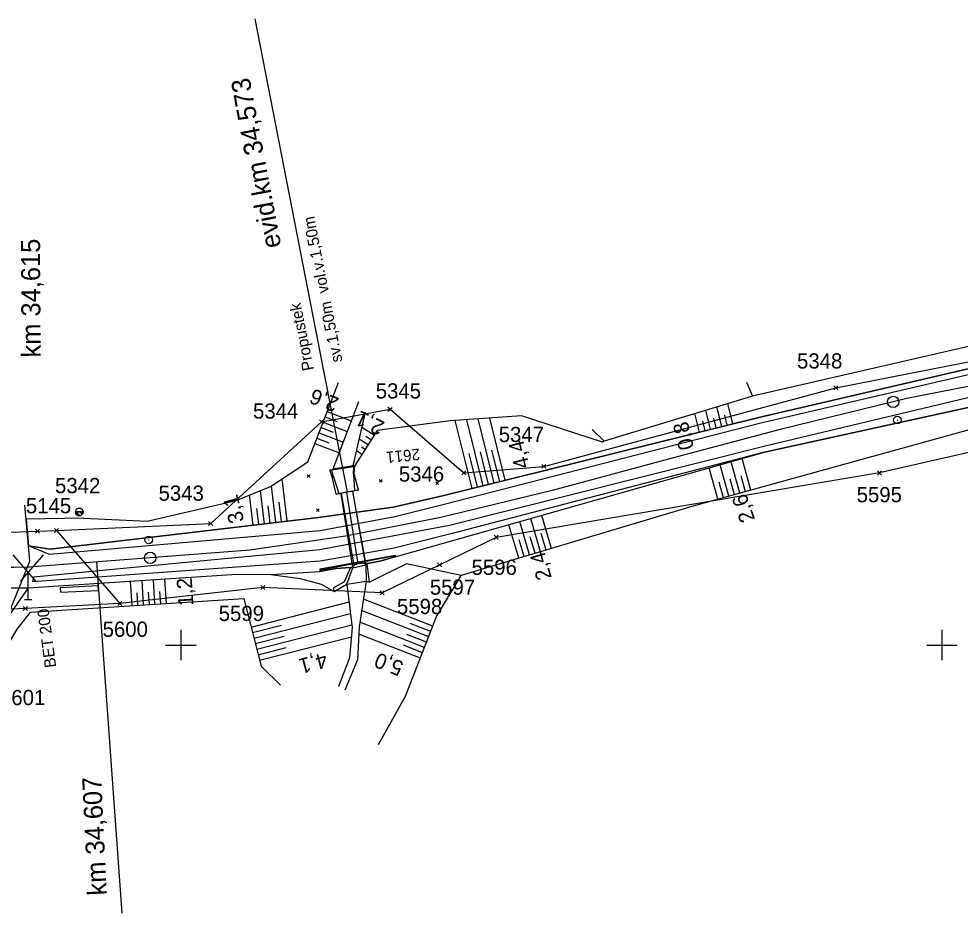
# Model space of a CAD drawing. Extents: x -805730 to -804640, y -1150889 to -1150366.
# Drawn here: x -805421.3 to -805297.6, y -1150735.2 to -1150617.7 of the extents above; entities that cross this region are included whole.
import ezdxf

# ---------------------------------------------------------------- set-up
doc = ezdxf.new("R2010")
doc.units = 0
for name, color, linetype in [('0381KM032-037P - Vrstva 1', 7, 'Continuous'), ('0381KM032-037P - Vrstva 17', 7, 'Continuous'), ('0381KM032-037P - Vrstva 19', 7, 'Continuous'), ('0381KM032-037P - Vrstva 36', 7, 'Continuous'), ('0381KM032-037P - Vrstva 4', 7, 'Continuous'), ('0381KM032-037P - Vrstva 48', 7, 'Continuous'), ('0381KM032-037P - Vrstva 49', 7, 'Continuous'), ('0381KM032-037P - Vrstva 51', 7, 'Continuous'), ('0381KM032-037P - Vrstva 55', 7, 'Continuous'), ('0381KM032-037P - Vrstva 57', 7, 'Continuous'), ('0381KM032-037P - Vrstva 7', 7, 'Continuous'), ('0381KM032-037P - Vrstva 9', 7, 'Continuous'), ('krizky_1000 - Vrstva 1', 7, 'Continuous'), ('szdc - hran DP', 7, 'Continuous'), ('szdc - szdc_cislo', 7, 'Continuous'), ('szdc - szdc_krizek', 7, 'Continuous')]:
    doc.layers.add(name, color=color, linetype=linetype)

msp = doc.modelspace()

# ---------------------------------------------------------------- linework, layer by layer
at = {"layer": '0381KM032-037P - Vrstva 1'}
for points in [[(-805262.34, -1150660.99), (-805275.34, -1150662.5), (-805288.75, -1150664.54), (-805289.64, -1150664.68), (-805304.6, -1150667.62), (-805306.42, -1150668.06)], [(-805306.42, -1150668.06), (-805321.24, -1150671.67), (-805334.8, -1150675.29), (-805351.21, -1150679.7), (-805364.56, -1150682.93)], [(-805364.56, -1150682.93), (-805366.04, -1150683.29), (-805378.36, -1150685.71), (-805390.91, -1150687.55), (-805419.96, -1150689.78), (-805423.96, -1150689.8), (-805433.29, -1150689.8), (-805447.38, -1150689.21), (-805460.61, -1150688.07), (-805473.24, -1150686.41), (-805486.12, -1150684.11), (-805496.07, -1150681.84)]]:
    msp.add_lwpolyline(points, dxfattribs=at)
at = {"layer": '0381KM032-037P - Vrstva 17'}
msp.add_lwpolyline([(-805325.7, -1150665.45), (-805324.89, -1150667.28), (-805344.39, -1150673.21), (-805345.97, -1150671.67)], dxfattribs=at)
at = {"layer": '0381KM032-037P - Vrstva 19'}
for p, q in [((-805378.12, -1150679.9), (-805390.23, -1150617.73)), ((-805380.17, -1150676.97), (-805377.25, -1150676.53)), ((-805377.12, -1150676.41), (-805377.25, -1150676.53)), ((-805377.23, -1150677.51), (-805377.12, -1150676.41)), ((-805380.42, -1150677), (-805380.17, -1150676.97)), ((-805380.12, -1150677.92), (-805380.42, -1150677)), ((-805378.95, -1150680.08), (-805377.25, -1150689.53)), ((-805377.4, -1150689.87), (-805378.93, -1150680.13)), ((-805378.22, -1150679.93), (-805376.73, -1150689.34)), ((-805377.44, -1150679.8), (-805375.79, -1150689.3)), ((-805377.44, -1150679.84), (-805375.71, -1150689.44)), ((-805371.83, -1150688.19), (-805372.13, -1150688.5)), ((-805381.67, -1150690), (-805381.78, -1150690.33)), ((-805425.41, -1150692.47), (-805420.07, -1150692.47)), ((-805378.2, -1150692.01), (-805375.64, -1150691.6))]:
    msp.add_line(p, q, dxfattribs=at)
for points in [[(-805379.92, -1150677.91), (-805380.17, -1150676.97), (-805380.03, -1150676.88), (-805377.35, -1150676.44)], [(-805377.3, -1150677.55), (-805377.25, -1150676.53), (-805377.35, -1150676.44)], [(-805377.44, -1150679.8), (-805377.44, -1150679.84), (-805377.2, -1150679.71), (-805376.64, -1150679.64), (-805377.23, -1150677.51), (-805377.3, -1150677.55), (-805377.2, -1150679.71)], [(-805379.6, -1150680.17), (-805380.12, -1150677.92), (-805379.92, -1150677.91), (-805379.23, -1150680.09)], [(-805376.64, -1150679.64), (-805379.6, -1150680.17), (-805379.23, -1150680.09), (-805378.93, -1150680.13), (-805378.95, -1150680.08)], [(-805377.25, -1150689.53), (-805377.4, -1150689.87), (-805377.71, -1150689.8), (-805379.64, -1150689.94), (-805381.78, -1150690.33), (-805381.61, -1150690.16), (-805381.67, -1150690), (-805371.83, -1150688.19), (-805371.8, -1150688.29), (-805381.61, -1150690.16)], [(-805371.8, -1150688.29), (-805372.13, -1150688.5), (-805373.84, -1150688.99), (-805375.5, -1150689.3), (-805375.71, -1150689.44), (-805375.79, -1150689.3)], [(-805377.71, -1150689.8), (-805378.52, -1150691.68), (-805379.98, -1150692.52), (-805379.86, -1150692.97), (-805378.2, -1150692.01), (-805377.4, -1150689.87)], [(-805375.71, -1150689.44), (-805375.64, -1150691.6), (-805375.2, -1150691.74), (-805375.5, -1150689.3)]]:
    msp.add_lwpolyline(points, dxfattribs=at)
for centre, major_axis, ratio, start_param, end_param in [((-805378.2, -1150679.95), (-0.792, -0.149), 0.032025, 3.416243, 5.97224), ((-805376.52, -1150689.46), (-0.761, -0.129), 0.198559, 3.38498, 5.924926)]:
    msp.add_ellipse(centre, major_axis=major_axis, ratio=ratio, start_param=start_param, end_param=end_param, dxfattribs=at)
at = {"layer": '0381KM032-037P - Vrstva 36'}
for p, q in [((-805413.84, -1150682.5), (-805412.84, -1150682.5)), ((-805412.84, -1150682.5), (-805413.84, -1150682.5)), ((-805413.28, -1150683), (-805413.77, -1150682.5)), ((-805412.94, -1150682.8), (-805413.24, -1150682.5))]:
    msp.add_line(p, q, dxfattribs=at)
msp.add_circle((-805413.34, -1150682.5), 0.503, dxfattribs=at)
msp.add_arc((-805413.34, -1150682.5), 0.503, 180, 0, dxfattribs=at)
at = {"layer": '0381KM032-037P - Vrstva 4'}
for p, q in [((-805422.05, -1150688.15), (-805419.05, -1150691.65)), ((-805421.05, -1150691.65), (-805418.05, -1150688.15)), ((-805423.96, -1150689.8), (-805419.82, -1150689.74)), ((-805420.05, -1150694), (-805420.05, -1150690.5)), ((-805420.55, -1150694), (-805419.55, -1150694))]:
    msp.add_line(p, q, dxfattribs=at)
for points in [[(-805228.99, -1150656.61), (-805257.13, -1150657.62), (-805260.23, -1150658.03), (-805264.49, -1150659.11), (-805283.86, -1150661.58), (-805295.64, -1150663.5), (-805324.06, -1150670.09), (-805365.63, -1150680.4), (-805372.09, -1150681.89), (-805381.91, -1150683.24), (-805417.14, -1150687.42), (-805420, -1150686.97)], [(-805212.28, -1150657.22), (-805228.89, -1150657.63), (-805258.88, -1150659.27), (-805264.46, -1150659.8), (-805283.61, -1150662.28), (-805295.6, -1150664.3), (-805323.97, -1150670.91), (-805365.39, -1150681.52), (-805371.9, -1150683.14), (-805381.67, -1150685.01), (-805417.27, -1150688.09), (-805420, -1150686.97)], [(-805212.01, -1150660.08), (-805229.13, -1150661), (-805258.58, -1150662.1), (-805264.18, -1150662.62), (-805283.43, -1150665.36), (-805294.93, -1150667.11), (-805323.21, -1150673.86), (-805364.72, -1150684.28), (-805371.95, -1150685.67), (-805381.73, -1150687.49), (-805401.63, -1150689.36), (-805419.33, -1150691.07), (-805419.49, -1150691.68)], [(-805225.57, -1150661.42), (-805229.16, -1150661.68), (-805258.55, -1150662.93), (-805264.16, -1150663.27), (-805283.37, -1150665.88), (-805323.33, -1150674.68), (-805364.37, -1150685.33), (-805371.95, -1150687.26), (-805381.71, -1150688.97), (-805419.49, -1150691.68)]]:
    msp.add_lwpolyline(points, dxfattribs=at)
at = {"layer": '0381KM032-037P - Vrstva 48'}
for p, q in [((-805330.39, -1150671.66), (-805331.01, -1150669.14)), ((-805328.93, -1150671.3), (-805329.57, -1150668.7)), ((-805327.47, -1150670.94), (-805328.14, -1150668.27)), ((-805381.03, -1150670.01), (-805379.45, -1150670.62)), ((-805380.75, -1150669.31), (-805377.62, -1150670.53)), ((-805360.28, -1150679.07), (-805362.44, -1150670.39)), ((-805358.83, -1150678.71), (-805360.92, -1150670.29)), ((-805357.37, -1150678.35), (-805359.4, -1150670.18)), ((-805331.84, -1150672.02), (-805332.45, -1150669.58)), ((-805329.66, -1150671.48), (-805329.97, -1150670.2)), ((-805328.2, -1150671.12), (-805328.53, -1150669.8)), ((-805381.57, -1150671.41), (-805379.99, -1150672.02)), ((-805381.3, -1150670.71), (-805378.15, -1150671.93)), ((-805374.6, -1150672.41), (-805376.2, -1150671.41)), ((-805361.74, -1150679.43), (-805363.95, -1150670.5)), ((-805331.11, -1150671.84), (-805331.42, -1150670.6)), ((-805382.11, -1150672.81), (-805380.53, -1150673.42)), ((-805381.84, -1150672.11), (-805378.68, -1150673.33)), ((-805375, -1150673.05), (-805375.68, -1150672.61)), ((-805382.38, -1150673.51), (-805379.21, -1150674.74)), ((-805375.4, -1150673.68), (-805376.55, -1150672.96)), ((-805375.8, -1150674.31), (-805376.26, -1150674.02)), ((-805376.2, -1150674.95), (-805376.9, -1150674.5)), ((-805361.01, -1150679.25), (-805362.1, -1150674.85)), ((-805359.56, -1150678.89), (-805360.62, -1150674.62)), ((-805358.1, -1150678.53), (-805359.13, -1150674.38)), ((-805327.99, -1150680.45), (-805329.14, -1150676.32)), ((-805326.55, -1150680.05), (-805327.69, -1150675.91)), ((-805325.1, -1150679.65), (-805326.25, -1150675.51)), ((-805329.44, -1150680.85), (-805330.58, -1150676.73)), ((-805325.82, -1150679.85), (-805326.4, -1150677.78)), ((-805387.51, -1150683.91), (-805388.09, -1150679.07)), ((-805386.02, -1150683.73), (-805386.68, -1150678.15)), ((-805328.71, -1150680.65), (-805329.29, -1150678.59)), ((-805327.27, -1150680.25), (-805327.84, -1150678.19)), ((-805390.49, -1150684.26), (-805390.96, -1150680.28)), ((-805389, -1150684.08), (-805389.52, -1150679.69)), ((-805386.77, -1150683.82), (-805387.08, -1150681.21)), ((-805389.75, -1150684.17), (-805389.99, -1150682.08)), ((-805388.26, -1150684), (-805388.53, -1150681.7)), ((-805354.17, -1150688.16), (-805355.47, -1150683.78)), ((-805352.73, -1150687.73), (-805354.03, -1150683.37)), ((-805351.29, -1150687.3), (-805352.58, -1150682.96)), ((-805355.6, -1150688.59), (-805356.92, -1150684.19)), ((-805354.89, -1150688.37), (-805355.54, -1150686.18)), ((-805353.45, -1150687.94), (-805354.1, -1150685.76)), ((-805352.01, -1150687.52), (-805352.66, -1150685.34)), ((-805403.39, -1150694.62), (-805403.59, -1150691.39)), ((-805401.89, -1150694.52), (-805402.09, -1150691.3)), ((-805406.38, -1150694.81), (-805406.59, -1150691.59)), ((-805404.88, -1150694.71), (-805405.09, -1150691.49)), ((-805405.63, -1150694.76), (-805405.73, -1150693.15)), ((-805404.13, -1150694.66), (-805404.24, -1150693.05)), ((-805402.64, -1150694.57), (-805402.74, -1150692.96)), ((-805390.77, -1150697.63), (-805377.9, -1150694.34)), ((-805366.89, -1150697.51), (-805376.01, -1150693.96)), ((-805390.4, -1150699.08), (-805377.71, -1150695.84)), ((-805367.43, -1150698.91), (-805376.24, -1150695.48)), ((-805390.59, -1150698.36), (-805386.75, -1150697.38)), ((-805390.03, -1150700.54), (-805377.53, -1150697.34)), ((-805367.98, -1150700.31), (-805376.48, -1150697)), ((-805367.16, -1150698.21), (-805369.85, -1150697.16)), ((-805390.21, -1150699.81), (-805386.44, -1150698.85)), ((-805368.52, -1150701.71), (-805376.62, -1150698.55)), ((-805367.71, -1150699.61), (-805370.3, -1150698.6)), ((-805389.66, -1150701.99), (-805377.59, -1150698.91)), ((-805368.25, -1150701.01), (-805370.75, -1150700.03)), ((-805389.84, -1150701.27), (-805386.15, -1150700.32))]:
    msp.add_line(p, q, dxfattribs=at)
at = {"layer": '0381KM032-037P - Vrstva 49'}
for p, q in [((-805383.32, -1150675.93), (-805379.28, -1150665.5)), ((-805376.67, -1150668.04), (-805380.03, -1150676.88)), ((-805377.35, -1150676.44), (-805375.74, -1150669.42)), ((-805374.21, -1150671.8), (-805377.12, -1150676.41)), ((-805377.35, -1150676.44), (-805380.03, -1150676.88)), ((-805377.12, -1150676.41), (-805377.35, -1150676.44)), ((-805383.03, -1150677.64), (-805383.38, -1150678)), ((-805383.38, -1150677.64), (-805383.02, -1150678)), ((-805373.92, -1150678.26), (-805373.56, -1150678.61)), ((-805373.56, -1150678.26), (-805373.91, -1150678.61)), ((-805366.14, -1150678.54), (-805366.49, -1150678.89)), ((-805366.49, -1150678.54), (-805366.13, -1150678.89)), ((-805381.8, -1150682.09), (-805382.15, -1150682.45)), ((-805382.15, -1150682.09), (-805381.8, -1150682.44))]:
    msp.add_line(p, q, dxfattribs=at)
for points in [[(-805420, -1150686.97), (-805417.14, -1150687.42), (-805381.91, -1150683.24), (-805372.09, -1150681.89), (-805365.63, -1150680.4), (-805324.06, -1150670.09), (-805295.64, -1150663.5), (-805283.86, -1150661.58), (-805264.49, -1150659.11)], [(-805372.13, -1150688.5), (-805323.33, -1150674.68), (-805283.37, -1150665.88), (-805264.16, -1150663.27), (-805258.55, -1150662.93), (-805229.16, -1150661.68), (-805225.47, -1150661.83)], [(-805296.52, -1150660.78), (-805324.89, -1150667.28), (-805344.39, -1150673.21)], [(-805229.52, -1150663.36), (-805258.94, -1150664.75), (-805264.69, -1150666.1), (-805283.13, -1150668.03), (-805332.88, -1150681.81), (-805363.18, -1150690.85)], [(-805344.39, -1150673.21), (-805344.61, -1150673.34), (-805355.22, -1150669.89), (-805364.63, -1150670.55), (-805374.21, -1150671.8)], [(-805412.74, -1150683.31), (-805404.41, -1150683.71), (-805392.74, -1150681.01), (-805388.23, -1150679.16), (-805383.32, -1150675.93)], [(-805412.74, -1150683.31), (-805420.31, -1150683.48), (-805420, -1150686.97)], [(-805420.07, -1150692.47), (-805392.63, -1150690.68), (-805388.18, -1150690.75), (-805381.78, -1150690.33), (-805379.64, -1150689.94), (-805377.71, -1150689.8), (-805377.4, -1150689.87), (-805375.71, -1150689.44), (-805375.5, -1150689.3), (-805373.84, -1150688.99), (-805372.13, -1150688.5)], [(-805363.18, -1150690.85), (-805370.35, -1150689.33), (-805375.2, -1150691.74), (-805375.64, -1150691.6)], [(-805388.18, -1150690.75), (-805384.32, -1150691.25), (-805381.55, -1150691.98), (-805379.86, -1150692.97), (-805378.2, -1150692.01), (-805377.48, -1150697.71), (-805377.85, -1150701.68), (-805379.27, -1150705.45)], [(-805374.03, -1150713.04), (-805370.47, -1150706.7), (-805366.4, -1150696.26), (-805363.18, -1150690.85)], [(-805420.07, -1150692.47), (-805422.84, -1150696.5), (-805425.52, -1150700.88)], [(-805378.2, -1150692.01), (-805375.64, -1150691.6), (-805376.57, -1150697.62), (-805376.78, -1150701.96), (-805378.44, -1150705.91)], [(-805419.74, -1150695.67), (-805391.73, -1150693.87), (-805389.46, -1150702.77), (-805386.92, -1150705.25)], [(-805423.96, -1150702.03), (-805421.5, -1150697.89), (-805419.74, -1150695.67)]]:
    msp.add_lwpolyline(points, dxfattribs=at)
at = {"layer": '0381KM032-037P - Vrstva 51'}
msp.add_lwpolyline([(-805425.52, -1150700.88), (-805422.84, -1150696.5), (-805419.83, -1150688.97), (-805420, -1150686.97), (-805420.48, -1150681.6)], dxfattribs=at)
at = {"layer": '0381KM032-037P - Vrstva 55'}
msp.add_line((-805416.34, -1150684.94), (-805408.01, -1150694.56), dxfattribs=at)
at = {"layer": '0381KM032-037P - Vrstva 7'}
for p, q in [((-805305.9, -1150670.45), (-805305.8, -1150670.45)), ((-805404.26, -1150686.19), (-805404.16, -1150686.19))]:
    msp.add_line(p, q, dxfattribs=at)
for centre, radius in [((-805306.42, -1150668.06), 0.75), ((-805305.85, -1150670.45), 0.5), ((-805404.21, -1150686.19), 0.5), ((-805404.03, -1150688.55), 0.75)]:
    msp.add_circle(centre, radius, dxfattribs=at)
at = {"layer": '0381KM032-037P - Vrstva 9'}
for p, q in [((-805411.08, -1150689.08), (-805407.73, -1150735.22)), ((-805410.84, -1150692.23), (-805415.83, -1150692.47)), ((-805415.83, -1150692.47), (-805415.8, -1150693.06)), ((-805410.84, -1150692.23), (-805410.86, -1150691.64)), ((-805410.81, -1150692.82), (-805410.84, -1150692.23)), ((-805415.8, -1150693.06), (-805410.81, -1150692.82))]:
    msp.add_line(p, q, dxfattribs=at)
at = {"layer": 'krizky_1000 - Vrstva 1'}
for points in [[(-805400, -1150698), (-805400, -1150702)], [(-805300, -1150698), (-805300, -1150702)], [(-805402, -1150700), (-805398, -1150700)], [(-805302, -1150700), (-805298, -1150700)]]:
    msp.add_lwpolyline(points, dxfattribs=at)
at = {"layer": 'szdc - hran DP'}
for p, q in [((-805313.93, -1150666.21), (-805288.99, -1150661.29)), ((-805352.32, -1150676.52), (-805313.93, -1150666.21)), ((-805267.02, -1150667.87), (-805308.19, -1150677.39)), ((-805381.52, -1150670.67), (-805372.51, -1150669.03)), ((-805372.51, -1150669.03), (-805362.8, -1150677.38)), ((-805396.07, -1150684.02), (-805381.52, -1150670.67)), ((-805362.8, -1150677.38), (-805352.32, -1150676.52)), ((-805308.19, -1150677.39), (-805358.57, -1150685.85)), ((-805416.34, -1150684.94), (-805396.07, -1150684.02)), ((-805423.42, -1150685.2), (-805418.81, -1150685.03)), ((-805418.81, -1150685.03), (-805416.34, -1150684.94)), ((-805358.57, -1150685.85), (-805365.99, -1150689.46)), ((-805365.99, -1150689.46), (-805373.55, -1150693.14)), ((-805389.21, -1150692.42), (-805408.01, -1150694.56)), ((-805373.55, -1150693.14), (-805389.21, -1150692.42)), ((-805408.01, -1150694.56), (-805420.42, -1150695.2)), ((-805420.42, -1150695.2), (-805426.08, -1150695.49))]:
    msp.add_line(p, q, dxfattribs=at)
at = {"layer": 'szdc - szdc_krizek'}
for p, q in [((-805313.67, -1150666.48), (-805314.2, -1150665.95)), ((-805314.2, -1150666.48), (-805313.67, -1150665.95)), ((-805372.24, -1150669.29), (-805372.78, -1150668.77)), ((-805372.78, -1150669.29), (-805372.24, -1150668.77)), ((-805381.26, -1150670.94), (-805381.79, -1150670.41)), ((-805381.79, -1150670.94), (-805381.26, -1150670.41)), ((-805352.06, -1150676.78), (-805352.59, -1150676.26)), ((-805352.59, -1150676.78), (-805352.06, -1150676.26)), ((-805362.54, -1150677.65), (-805363.07, -1150677.11)), ((-805363.07, -1150677.65), (-805362.54, -1150677.11)), ((-805307.93, -1150677.66), (-805308.46, -1150677.12)), ((-805308.46, -1150677.66), (-805307.93, -1150677.12)), ((-805395.81, -1150684.28), (-805396.34, -1150683.76)), ((-805396.34, -1150684.28), (-805395.81, -1150683.76)), ((-805418.55, -1150685.29), (-805419.08, -1150684.77)), ((-805419.08, -1150685.29), (-805418.55, -1150684.77)), ((-805416.08, -1150685.21), (-805416.61, -1150684.68)), ((-805416.61, -1150685.21), (-805416.08, -1150684.68)), ((-805358.31, -1150686.11), (-805358.84, -1150685.58)), ((-805358.84, -1150686.11), (-805358.31, -1150685.58)), ((-805365.72, -1150689.73), (-805366.26, -1150689.2)), ((-805366.26, -1150689.73), (-805365.72, -1150689.2)), ((-805388.95, -1150692.69), (-805389.48, -1150692.16)), ((-805389.48, -1150692.69), (-805388.95, -1150692.16)), ((-805373.29, -1150693.41), (-805373.82, -1150692.88)), ((-805373.82, -1150693.41), (-805373.29, -1150692.88)), ((-805420.16, -1150695.47), (-805420.69, -1150694.94)), ((-805420.69, -1150695.47), (-805420.16, -1150694.94)), ((-805407.74, -1150694.82), (-805408.28, -1150694.29)), ((-805408.28, -1150694.82), (-805407.74, -1150694.29))]:
    msp.add_line(p, q, dxfattribs=at)

# ---------------------------------------------------------------- texts
at = {"layer": '0381KM032-037P - Vrstva 19'}
for s, height, rotation, p in [('evid.km 34,573', 2.5, 100.6945, (-805386.78, -1150647.62)), ('sv.1,50m  vol.v.1,50m', 1.4999, 101.0532, (-805378.75, -1150662.72)), ('Propustek', 1.5, 101.1547, (-805382.51, -1150663.81)), ('BET 200', 1.5, 97.5063, (-805416.36, -1150702.88))]:
    msp.add_text(s, height=height, rotation=rotation, dxfattribs=at).set_placement(p)
at = {"layer": '0381KM032-037P - Vrstva 4'}
msp.add_text('km 34,615', height=2.5, rotation=90.3142, dxfattribs=at).set_placement((-805418.41, -1150662.22))
at = {"layer": '0381KM032-037P - Vrstva 48'}
for s, height, rotation, p in [('2,6', 2, 158.8025, (-805379.08, -1150667.6)), ('2,1', 2, 154.4647, (-805373.08, -1150670.75)), ('0,8', 1.99, 103.9155, (-805332.56, -1150674.1)), ('4,4', 2, 103.9188, (-805354.16, -1150676.55)), ('3,1', 2, 104.8055, (-805391.65, -1150683.68)), ('2,6', 2, 109.5492, (-805324.53, -1150683.48)), ('2,4', 2, 105.8138, (-805351.25, -1150691.15)), ('1,2', 2, 93.6817, (-805398.33, -1150694.8)), ('4,1', 2, 194.3297, (-805381.04, -1150700.95)), ('5,0', 2, 158.7077, (-805370.58, -1150702.28))]:
    msp.add_text(s, height=height, rotation=rotation, dxfattribs=at).set_placement(p)
at = {"layer": '0381KM032-037P - Vrstva 57'}
msp.add_text('2611', height=1.5, rotation=185.7179, dxfattribs=at).set_placement((-805368.65, -1150674.18))
at = {"layer": '0381KM032-037P - Vrstva 9'}
msp.add_text('km 34,607', height=2.5, rotation=92.7706, dxfattribs=at).set_placement((-805409.71, -1150732.84))
at = {"layer": 'szdc - szdc_cislo'}
for s, p in [('5348', (-805319.04, -1150663.67)), ('5345', (-805374.39, -1150667.61)), ('5344', (-805390.51, -1150670.25)), ('5347', (-805358.23, -1150673.33)), ('5346', (-805371.35, -1150678.53)), ('5342', (-805416.52, -1150680.05)), ('5343', (-805402.92, -1150681.04)), ('5595', (-805311.21, -1150681.24)), ('5145', (-805420.35, -1150682.69)), ('5596', (-805361.8, -1150690.78)), ('5597', (-805367.28, -1150693.39)), ('5598', (-805371.6, -1150695.93)), ('5599', (-805395.02, -1150696.84)), ('5600', (-805410.27, -1150698.92)), ('5601', (-805423.75, -1150707.89))]:
    msp.add_text(s, height=2, dxfattribs=at).set_placement(p)

doc.saveas('drawing.dxf')
